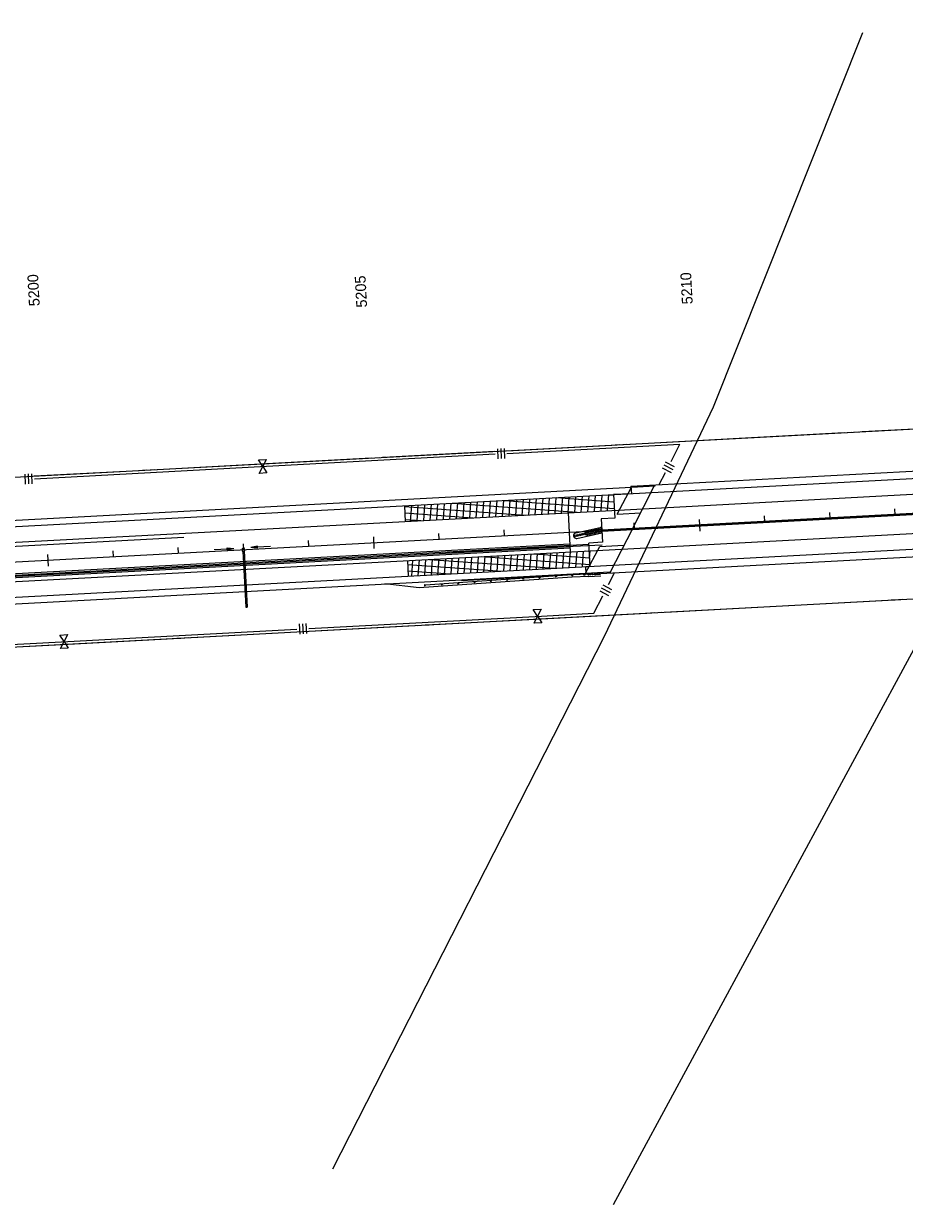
# Model space of a CAD drawing. Extents: x 192699 to 285914, y 194342 to 233219.
# Drawn here: x 264587 to 265937, y 224538 to 226348 of the extents above; entities that cross this region are included whole.
import ezdxf

# ---------------------------------------------------------------- set-up
doc = ezdxf.new("R2010")
doc.units = 0
for name, color, linetype in [('Barrier Wall', 7, 'Continuous'), ('BRIDGE', 7, 'Continuous'), ('CENT LINE', 7, 'Continuous'), ('CONCRETE', 7, 'Continuous'), ('DRAINAGE', 7, 'Continuous'), ('DRAINAGE ARROWS', 7, 'Continuous'), ('Flood Plain', 7, 'Continuous'), ('GUARDRAIL', 7, 'Continuous'), ('PAVEMENT TRANSITION', 7, 'Continuous'), ('R-W - CofA', 7, 'Continuous'), ('R_Draft', 7, 'Continuous'), ('R_Water Annot', 7, 'Continuous'), ('ROAD', 7, 'Continuous'), ('SHOULDER', 7, 'Continuous'), ('STATIONING1', 7, 'Continuous'), ('WRSF', 7, 'Continuous')]:
    doc.layers.add(name, color=color, linetype=linetype)

msp = doc.modelspace()

# ---------------------------------------------------------------- linework, layer by layer
at = {"layer": 'Barrier Wall'}
for p, q in [((265473.5, 225571.9), (266128.8, 225607)), ((265473.6, 225569.9), (266128.9, 225605)), ((265473.6, 225569.9), (265473.5, 225571.9)), ((265223.8, 225558.5), (265223.9, 225556.5))]:
    msp.add_line(p, q, dxfattribs=at)
at = {"layer": 'BRIDGE'}
for p, q in [((265518.2, 225639), (266130.7, 225671.8)), ((265518.2, 225639), (265518.9, 225627.4)), ((265518.9, 225627.4), (265491.4, 225626)), ((265491.4, 225626), (265493.3, 225590)), ((265493.3, 225590), (265472.6, 225588.9)), ((265472.6, 225588.9), (265474.5, 225553)), ((265520.4, 225573.4), (265486.1, 225505.9)), ((265474.5, 225553), (265453.8, 225551.8)), ((265455.7, 225515.9), (265453.8, 225551.8)), ((265471.7, 225505.2), (266084.2, 225538)), ((265455.7, 225515.9), (265449, 225515.5)), ((265449.6, 225504), (265449, 225515.5))]:
    msp.add_line(p, q, dxfattribs=at)
for points in [[(265497.2, 225596.2), (265519.2, 225637.5)], [(265422, 225598.2), (265425.2, 225538.3)], [(265448.7, 225505.5), (265470.7, 225546.7)]]:
    msp.add_lwpolyline(points, dxfattribs=at)
at = {"layer": 'CENT LINE'}
msp.add_line((253740.3, 224942.3), (269263.7, 225774), dxfattribs=at)
at = {"layer": 'CONCRETE'}
for p, q in [((265520.4, 225573.4), (265554.7, 225641)), ((262014.4, 225367.6), (265424.6, 225550.3)), ((262014.5, 225363.6), (265424.8, 225546.3))]:
    msp.add_line(p, q, dxfattribs=at)
at = {"layer": 'DRAINAGE'}
for p, q in [((264923.3, 225539.4), (264927.9, 225453.6)), ((264925.3, 225539.6), (264929.9, 225453.7))]:
    msp.add_line(p, q, dxfattribs=at)
msp.add_lwpolyline([(264922.3, 225539.4), (264926.3, 225539.6), (264926.1, 225543.6), (264922.1, 225543.4)], close=True, dxfattribs=at)
msp.add_lwpolyline([(264927.9, 225453.6), (264929.9, 225453.7)], dxfattribs=at)
at = {"layer": 'DRAINAGE ARROWS'}
for p, q in [((264899.3, 225544.4), (264909.4, 225543.5)), ((264899.5, 225541.4), (264899.3, 225544.4)), ((264899.3, 225544.2), (264907.7, 225543.4)), ((264899.3, 225543.9), (264906, 225543.3)), ((264899.4, 225543.7), (264904.3, 225543.2)), ((264899.4, 225543.4), (264902.6, 225543.1)), ((264899.4, 225541.9), (264906, 225543.3)), ((264899.4, 225542.2), (264904.3, 225543.2)), ((264899.4, 225543.2), (264901, 225543)), ((264899.4, 225542.5), (264902.6, 225543.1)), ((264899.4, 225542.7), (264901, 225543)), ((264899.5, 225541.4), (264909.4, 225543.5)), ((264899.5, 225541.7), (264907.7, 225543.4)), ((264945.6, 225546.9), (264935.7, 225544.9)), ((264945.7, 225543.9), (264935.7, 225544.9)), ((264945.6, 225546.7), (264937.3, 225545)), ((264945.7, 225544.2), (264937.3, 225545)), ((264945.6, 225546.4), (264939, 225545.1)), ((264945.7, 225544.4), (264939, 225545.1)), ((264945.6, 225546.2), (264940.7, 225545.2)), ((264945.7, 225544.7), (264940.7, 225545.2)), ((264945.6, 225545.9), (264942.4, 225545.3)), ((264945.7, 225545), (264942.4, 225545.3)), ((264945.6, 225545.7), (264944.1, 225545.4)), ((264945.7, 225545.2), (264944.1, 225545.4)), ((264945.7, 225543.9), (264945.6, 225546.9))]:
    msp.add_line(p, q, dxfattribs=at)
at = {"layer": 'Flood Plain'}
for points in [[(265491.5, 224538.3), (265976.1, 225432.8), (266133, 225791.2), (266327.5, 226347.7)], [(265061.5, 224592.9), (265477.8, 225408.9), (265645, 225760.5), (265873.7, 226334.1)]]:
    msp.add_lwpolyline(points, dxfattribs=at)
at = {"layer": 'GUARDRAIL'}
for p, q in [((265474.2, 225548.3), (265229.9, 225537.4)), ((265453.4, 225504.8), (265258.5, 225493.8))]:
    msp.add_line(p, q, dxfattribs=at)
at = {"layer": 'PAVEMENT TRANSITION'}
for p, q in [((265391.9, 225596.6), (265393.6, 225620.7)), ((265401.9, 225597.1), (265403.7, 225621.3)), ((265404, 225621.3), (265492, 225614.9)), ((265412, 225597.7), (265413.7, 225621.8)), ((265422.1, 225598.2), (265423.8, 225622.3)), ((265432.1, 225598.8), (265433.9, 225622.9)), ((265442.2, 225599.3), (265443.9, 225623.4)), ((265452.3, 225599.8), (265454, 225624)), ((265462.3, 225600.4), (265464.1, 225624.5)), ((265472.4, 225600.9), (265474.1, 225625)), ((265482.5, 225601.4), (265484.2, 225625.6)), ((265483.9, 225625.6), (265491.5, 225625)), ((265171.1, 225608.8), (265172.4, 225584.8)), ((265171.2, 225608), (265355.9, 225594.7)), ((265180.5, 225585.3), (265182.3, 225609.4)), ((265190.6, 225585.8), (265192.3, 225609.9)), ((265200.6, 225586.4), (265202.4, 225610.5)), ((265210.7, 225586.9), (265212.4, 225611)), ((265220.8, 225587.4), (265222.5, 225611.6)), ((265230.8, 225588), (265232.6, 225612.1)), ((265240.9, 225588.5), (265242.6, 225612.6)), ((265244.3, 225612.7), (265435.8, 225598.9)), ((265251, 225589), (265252.7, 225613.2)), ((265261, 225589.6), (265262.8, 225613.7)), ((265271.1, 225590.1), (265272.8, 225614.3)), ((265281.2, 225590.7), (265282.9, 225614.8)), ((265291.2, 225591.2), (265293, 225615.3)), ((265301.3, 225591.7), (265303, 225615.9)), ((265311.4, 225592.3), (265313.1, 225616.4)), ((265321.4, 225592.8), (265323.2, 225616.9)), ((265324.2, 225617), (265492.5, 225604.9)), ((265331.5, 225593.4), (265333.2, 225617.5)), ((265341.6, 225593.9), (265343.3, 225618)), ((265351.6, 225594.4), (265353.4, 225618.6)), ((265361.7, 225595), (265363.4, 225619.1)), ((265371.7, 225595.5), (265373.5, 225619.6)), ((265381.8, 225596.1), (265383.5, 225620.2)), ((265171.7, 225597.9), (265276, 225590.4)), ((265172.2, 225587.8), (265196.2, 225586.1)), ((265272.9, 225506.1), (265274.6, 225530.2)), ((265282.9, 225506.6), (265284.7, 225530.8)), ((265289.4, 225531), (265455.5, 225519.1)), ((265293, 225507.2), (265294.7, 225531.3)), ((265303.1, 225507.7), (265304.8, 225531.8)), ((265313.1, 225508.3), (265314.9, 225532.4)), ((265323.2, 225508.8), (265324.9, 225532.9)), ((265333.2, 225509.3), (265335, 225533.5)), ((265343.3, 225509.9), (265345.1, 225534)), ((265353.4, 225510.4), (265355.1, 225534.5)), ((265363.4, 225511), (265365.2, 225535.1)), ((265369.2, 225535.3), (265455, 225529.1)), ((265373.5, 225511.5), (265375.2, 225535.6)), ((265383.6, 225512), (265385.3, 225536.2)), ((265393.6, 225512.6), (265395.4, 225536.7)), ((265403.7, 225513.1), (265405.4, 225537.2)), ((265413.8, 225513.6), (265415.5, 225537.8)), ((265423.8, 225514.2), (265425.6, 225538.3)), ((265433.9, 225514.7), (265435.6, 225538.9)), ((265444, 225515.3), (265445.7, 225539.4)), ((265449.1, 225539.6), (265454.5, 225539.2)), ((265454.9, 225528.3), (265455.8, 225539.9)), ((265175.6, 225524.9), (265176.9, 225501)), ((265175.9, 225519.1), (265321.1, 225508.7)), ((265182.3, 225501.2), (265184, 225525.4)), ((265192.3, 225501.8), (265194.1, 225525.9)), ((265202.4, 225502.3), (265204.1, 225526.5)), ((265209.5, 225526.7), (265400.9, 225513)), ((265212.5, 225502.9), (265214.2, 225527)), ((265222.5, 225503.4), (265224.3, 225527.5)), ((265232.6, 225503.9), (265234.3, 225528.1)), ((265242.7, 225504.5), (265244.4, 225528.6)), ((265252.7, 225505), (265254.5, 225529.1)), ((265262.8, 225505.6), (265264.5, 225529.7)), ((265176.5, 225509.1), (265241.2, 225504.4))]:
    msp.add_line(p, q, dxfattribs=at)
at = {"layer": 'R-W - CofA'}
for p, q in [((265313.5, 225696.1), (265314.3, 225680.8)), ((265318.6, 225696.4), (265319.4, 225681.1)), ((265323.7, 225696.7), (265324.5, 225681.4)), ((265579.8, 225676.9), (265593.2, 225703.4)), ((264947.3, 225679.3), (264959.3, 225679.9)), ((264953.9, 225669.2), (264947.3, 225679.3)), ((264959.3, 225679.9), (264953.9, 225669.2)), ((265570.9, 225676.1), (265584.5, 225669.2)), ((264589.2, 225657.3), (264590, 225642)), ((264594.3, 225657.6), (264595.1, 225642.3)), ((264599.4, 225657.9), (264600.2, 225642.6)), ((264948.4, 225658.5), (264953.9, 225669.2)), ((264960.4, 225659.1), (264948.4, 225658.5)), ((264953.9, 225669.2), (264960.4, 225659.1)), ((265561.7, 225641.3), (265571, 225659.7)), ((265566.3, 225667), (265579.9, 225660.1)), ((265568.6, 225671.6), (265582.2, 225664.6)), ((265484, 225488.4), (265493.1, 225506.3)), ((265470.4, 225478.5), (265484.1, 225471.6)), ((265472.7, 225483.1), (265486.4, 225476.1)), ((265475, 225487.6), (265488.7, 225480.7)), ((265461.5, 225444.2), (265475.1, 225471)), ((265368.6, 225449.7), (265380.7, 225450.3)), ((265375.2, 225439.6), (265368.6, 225449.7)), ((265380.7, 225450.3), (265375.2, 225439.6)), ((265009.7, 225427.7), (265010.5, 225412.3)), ((265014.8, 225427.9), (265015.7, 225412.6)), ((265019.9, 225428.2), (265020.8, 225412.9)), ((265369.7, 225428.8), (265375.2, 225439.6)), ((265381.8, 225429.5), (265369.7, 225428.8)), ((265375.2, 225439.6), (265381.8, 225429.5)), ((264642.7, 225410.8), (264654.7, 225411.4)), ((264649.3, 225400.7), (264642.7, 225410.8)), ((264654.7, 225411.4), (264649.3, 225400.7)), ((264643.8, 225389.9), (264649.3, 225400.7)), ((264655.9, 225390.6), (264643.8, 225389.9)), ((264649.3, 225400.7), (264655.9, 225390.6))]:
    msp.add_line(p, q, dxfattribs=at)
for points in [[(261904.8, 225509.9), (268431.7, 225859.6)], [(265872.9, 225722.5), (266052.4, 225732.1)], [(265517, 225703.4), (265684, 225712.4)], [(265684, 225712.4), (265845, 225721)], [(265850.2, 225721.3), (265856.4, 225721.6)], [(265861.6, 225721.9), (265867.8, 225722.2)], [(265328, 225693.3), (265489, 225701.9)], [(265328.2, 225689.2), (265593.2, 225703.4)], [(265494.2, 225702.2), (265500.4, 225702.6)], [(265505.6, 225702.8), (265511.8, 225703.2)], [(264959.6, 225673.6), (265120.7, 225682.2)], [(264959.9, 225669.5), (265309.9, 225688.3)], [(265125.8, 225682.5), (265132.1, 225682.8)], [(265137.2, 225683.1), (265143.4, 225683.4)], [(265148.6, 225683.7), (265309.6, 225692.3)], [(264603.7, 225654.5), (264764.7, 225663.1)], [(264603.9, 225650.4), (264959.9, 225669.5)], [(264769.8, 225663.4), (264776.1, 225663.7)], [(264781.2, 225664), (264787.5, 225664.4)], [(264792.6, 225664.6), (264959.6, 225673.6)], [(261904.6, 225249.5), (268432, 225599.2)], [(261904.6, 225249.5), (268432, 225599.2)], [(265750.6, 225455.6), (265911.9, 225464.2)], [(265917.1, 225464.5), (265923.4, 225464.8)], [(265928.5, 225465.1), (265934.8, 225465.5)], [(265024.4, 225420.8), (265381.2, 225439.9)], [(265381.2, 225439.9), (265461.5, 225444.2)], [(265381.4, 225435.8), (265542.8, 225444.5)], [(265548, 225444.7), (265554.2, 225445.1)], [(265559.4, 225445.3), (265565.6, 225445.7)], [(265570.8, 225446), (265750.6, 225455.6)], [(265024.7, 225416.7), (265186, 225425.3)], [(265191.2, 225425.6), (265197.4, 225425.9)], [(265202.6, 225426.2), (265208.9, 225426.6)], [(265214, 225426.8), (265381.4, 225435.8)], [(264655.3, 225401), (265006, 225419.8)], [(264655.5, 225396.9), (264816.9, 225405.6)], [(264822.1, 225405.8), (264828.3, 225406.2)], [(264833.5, 225406.5), (264839.7, 225406.8)], [(264844.9, 225407.1), (265006.3, 225415.7)], [(264298.5, 225381.9), (264655.3, 225401)], [(264488.1, 225387.9), (264655.5, 225396.9)]]:
    msp.add_lwpolyline(points, dxfattribs=at)
at = {"layer": 'R_Draft'}
for p, q in [((265433.6, 225567.2), (265471, 225575.4)), ((265435.4, 225558.9), (265473.7, 225567.3)), ((265473.7, 225567.3), (265473.4, 225573.6)), ((265428, 225503), (265253.4, 225490.7)), ((265428.3, 225499.5), (265303.5, 225490.7)), ((265453, 225504.2), (265428, 225503)), ((265453.2, 225500.7), (265428.2, 225499.5)), ((265453, 225504.2), (265471.7, 225505.2)), ((265453.2, 225500.7), (265471.9, 225501.7)), ((265193.8, 225483), (265141.2, 225489.1)), ((265303.5, 225490.7), (265193.8, 225483)), ((265201.7, 225488.1), (265203.5, 225487.2)), ((265201.7, 225488.1), (265201.9, 225486.1)), ((265201.9, 225486.1), (265203.5, 225487.2)), ((265253.4, 225490.7), (265203.5, 225487.2))]:
    msp.add_line(p, q, dxfattribs=at)
for centre, radius in [((265446.6, 225565.7), 1.38), ((265449.7, 225568.3), 1.38), ((265453.1, 225569.1), 1.38), ((265453.9, 225565.4), 1.38), ((265456.5, 225569.8), 1.38), ((265457.3, 225566.2), 1.38), ((265459.9, 225570.6), 1.38), ((265460.7, 225566.9), 1.38), ((265463.4, 225571.3), 1.38), ((265464.2, 225567.7), 1.38), ((265466.8, 225572.1), 1.38), ((265467.6, 225568.4), 1.38), ((265470.2, 225572.8), 1.38), ((265471, 225569.2), 1.38), ((265432.9, 225562.7), 1.38), ((265436.3, 225563.5), 1.38), ((265439.8, 225564.2), 1.38), ((265443.2, 225565), 1.38), ((265450.5, 225564.7), 1.38), ((265303.3, 225493.5), 0.75), ((265328.3, 225495.2), 0.75), ((265353.2, 225497), 0.75), ((265378.2, 225498.7), 0.75), ((265403.1, 225500.5), 0.75), ((265428, 225502.2), 0.75), ((265446.8, 225503.2), 0.75), ((265453, 225503.5), 0.75), ((265456.1, 225503.6), 0.75), ((265459.3, 225503.8), 0.75), ((265462.4, 225503.9), 0.75), ((265463.9, 225504), 0.75), ((265465.5, 225504.1), 0.75), ((265467.1, 225504.2), 0.75), ((265468.6, 225504.2), 0.75), ((265470.2, 225504.3), 0.75), ((265228.5, 225488.2), 0.75), ((265253.4, 225489.9), 0.75), ((265278.4, 225491.7), 0.75)]:
    msp.add_circle(centre, radius, dxfattribs=at)
for centre, radius, start, end in [((265434.5, 225563.1), 4.25, 102.314, 282.314), ((265471.4, 225573.5), 2, 2.8516, 102.314)]:
    msp.add_arc(centre, radius, start, end, dxfattribs=at)
at = {"layer": 'R_Water Annot'}
for p, q in [((264879.4, 225541.9), (264909.4, 225543.5)), ((264899.3, 225544.4), (264909.4, 225543.5)), ((264899.5, 225541.4), (264899.3, 225544.4)), ((264899.3, 225544.2), (264907.7, 225543.4)), ((264899.3, 225543.9), (264906, 225543.3)), ((264899.4, 225543.7), (264904.3, 225543.2)), ((264899.4, 225543.4), (264902.6, 225543.1)), ((264899.4, 225541.9), (264906, 225543.3)), ((264899.4, 225542.2), (264904.3, 225543.2)), ((264899.4, 225543.2), (264901, 225543)), ((264899.4, 225542.5), (264902.6, 225543.1)), ((264899.4, 225542.7), (264901, 225543)), ((264899.5, 225541.4), (264909.4, 225543.5)), ((264899.5, 225541.7), (264907.7, 225543.4)), ((264945.6, 225546.9), (264935.7, 225544.9)), ((264965.6, 225546.6), (264935.7, 225544.9)), ((264945.7, 225543.9), (264935.7, 225544.9)), ((264945.6, 225546.7), (264937.3, 225545)), ((264945.7, 225544.2), (264937.3, 225545)), ((264945.6, 225546.4), (264939, 225545.1)), ((264945.7, 225544.4), (264939, 225545.1)), ((264945.6, 225546.2), (264940.7, 225545.2)), ((264945.7, 225544.7), (264940.7, 225545.2)), ((264945.6, 225545.9), (264942.4, 225545.3)), ((264945.7, 225545), (264942.4, 225545.3)), ((264945.6, 225545.7), (264944.1, 225545.4)), ((264945.7, 225545.2), (264944.1, 225545.4)), ((264945.7, 225543.9), (264945.6, 225546.9))]:
    msp.add_line(p, q, dxfattribs=at)
at = {"layer": 'ROAD'}
for p, q in [((265550.1, 225629.1), (269260.9, 225827.9)), ((265536.9, 225604.4), (269262.1, 225803.9)), ((265503.9, 225542.5), (269265.4, 225744)), ((265490.7, 225517.8), (269266.6, 225720.1)), ((265519.2, 225637.5), (265555.6, 225639.4)), ((257860.4, 225217.1), (265550.1, 225629.1)), ((255085.2, 225044.4), (265536.9, 225604.4)), ((265497.2, 225596.2), (265533.6, 225598.2)), ((265470.7, 225546.7), (265507.2, 225548.7)), ((255121.9, 224986.3), (265503.9, 225542.5)), ((258372, 225136.4), (265490.7, 225517.8)), ((265448.7, 225505.5), (265485.2, 225507.5))]:
    msp.add_line(p, q, dxfattribs=at)
at = {"layer": 'SHOULDER'}
for p, q in [((257898.9, 225229.2), (265519.2, 225637.5)), ((257901, 225189.3), (264833.1, 225560.7)), ((257895.6, 225140.9), (265424.9, 225544.3)), ((258272.7, 225121.1), (265448.7, 225505.5))]:
    msp.add_line(p, q, dxfattribs=at)
at = {"layer": 'STATIONING1'}
for points in [[(265922.3, 225604), (265922.8, 225595)], [(265622.8, 225587.9), (265623.7, 225570)], [(265722.6, 225593.3), (265723.1, 225584.3)], [(265822.5, 225598.6), (265822.9, 225589.6)], [(265223.3, 225566.5), (265223.8, 225557.5)], [(265323.2, 225571.9), (265323.7, 225562.9)], [(265423, 225577.2), (265423.5, 225568.2)], [(265522.9, 225582.6), (265523.4, 225573.6)], [(264923.8, 225550.5), (264924.2, 225541.5)], [(265023.6, 225555.8), (265024.1, 225546.8)], [(265123.5, 225561.2), (265124.4, 225543.2)], [(264624.2, 225534.4), (264625.1, 225516.5)], [(264724, 225539.8), (264724.5, 225530.8)], [(264823.9, 225545.1), (264824.4, 225536.1)]]:
    msp.add_lwpolyline(points, dxfattribs=at)
at = {"layer": 'WRSF'}
msp.add_line((262014.4, 225365.6), (265453.9, 225549.8), dxfattribs=at)

# ---------------------------------------------------------------- texts
at = {"layer": 'STATIONING1'}
for s, p in [('5210', (265613, 225918)), ('5200', (264612.1, 225915.1)), ('5205', (265113.9, 225913))]:
    msp.add_text(s, height=16.5, rotation=93.0667, dxfattribs=at).set_placement(p)

doc.saveas('drawing.dxf')
